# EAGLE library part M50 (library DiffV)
SUB-D
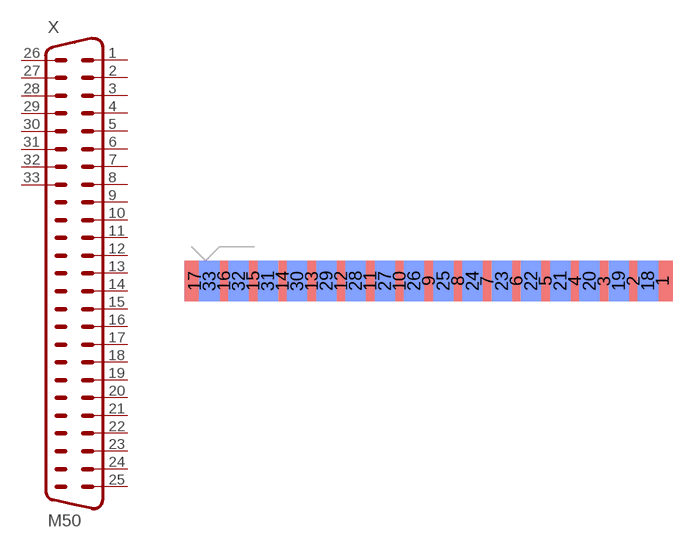
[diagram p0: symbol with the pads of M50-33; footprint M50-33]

Designator prefix X

## M50  [M50-33]
1  1  pas
2  2  pas
3  3  pas
4  4  pas
5  5  pas
6  6  pas
7  7  pas
8  8  pas
9  9  pas
10  10  pas
11  11  pas
12  12  pas
13  13  pas
14  14  pas
15  15  pas
16  16  pas
17  17  pas
18  18  pas
19  19  pas
20  20  pas
21  21  pas
22  22  pas
23  23  pas
24  24  pas
25  25  pas
26  26  pas
27  27  pas
28  28  pas
29  29  pas
30  30  pas
31  31  pas
32  32  pas
33  33  pas

## Footprint M50-33 (pad centres in mm)
2 Reihen von 3reihigem 50pol. SubD-Steckverbinder
smd 1.905 x 3.81: 1 22.149,-1.905; 2 19.38,-1.905; 3 16.612,-1.905; 4 13.843,-1.905; 5 11.074,-1.905; 6 8.306,-1.905; 7 5.537,-1.905; 8 2.769,-1.905; 9 0,-1.905; 10 -2.769,-1.905; 11 -5.537,-1.905; 12 -8.306,-1.905; 13 -11.074,-1.905; 14 -13.843,-1.905; 15 -16.612,-1.905; 16 -19.38,-1.905; 17 -22.149,-1.905
smd 1.905 x 3.81 bottom: 18 20.765,-1.905; 19 17.996,-1.905; 20 15.227,-1.905; 21 12.459,-1.905; 22 9.69,-1.905; 23 6.921,-1.905; 24 4.153,-1.905; 25 1.384,-1.905; 26 -1.384,-1.905; 27 -4.153,-1.905; 28 -6.921,-1.905; 29 -9.69,-1.905; 30 -12.459,-1.905; 31 -15.227,-1.905; 32 -17.996,-1.905; 33 -20.765,-1.905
